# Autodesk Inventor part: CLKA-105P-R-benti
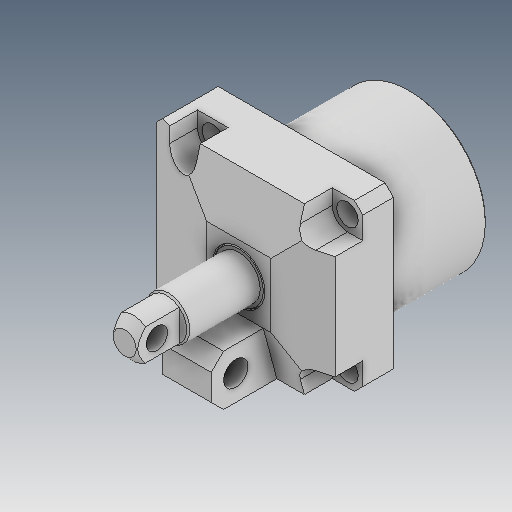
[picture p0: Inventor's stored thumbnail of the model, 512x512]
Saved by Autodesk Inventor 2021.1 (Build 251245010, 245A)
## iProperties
Created: 2018-07
Part Number: CLKA-105P-R-benti
Material: Ogólny
Document SubType Name: Modeling
Designer: user
Density: 1 g/cm^3
Appearance: Domyślna
Author: user
Revision Number: ÈÎºÎ
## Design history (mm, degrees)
feature "Í¹Ì¨-À­Éì4"
node "Bryła1"
